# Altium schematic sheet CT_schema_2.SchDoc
size 566 x 421 mm
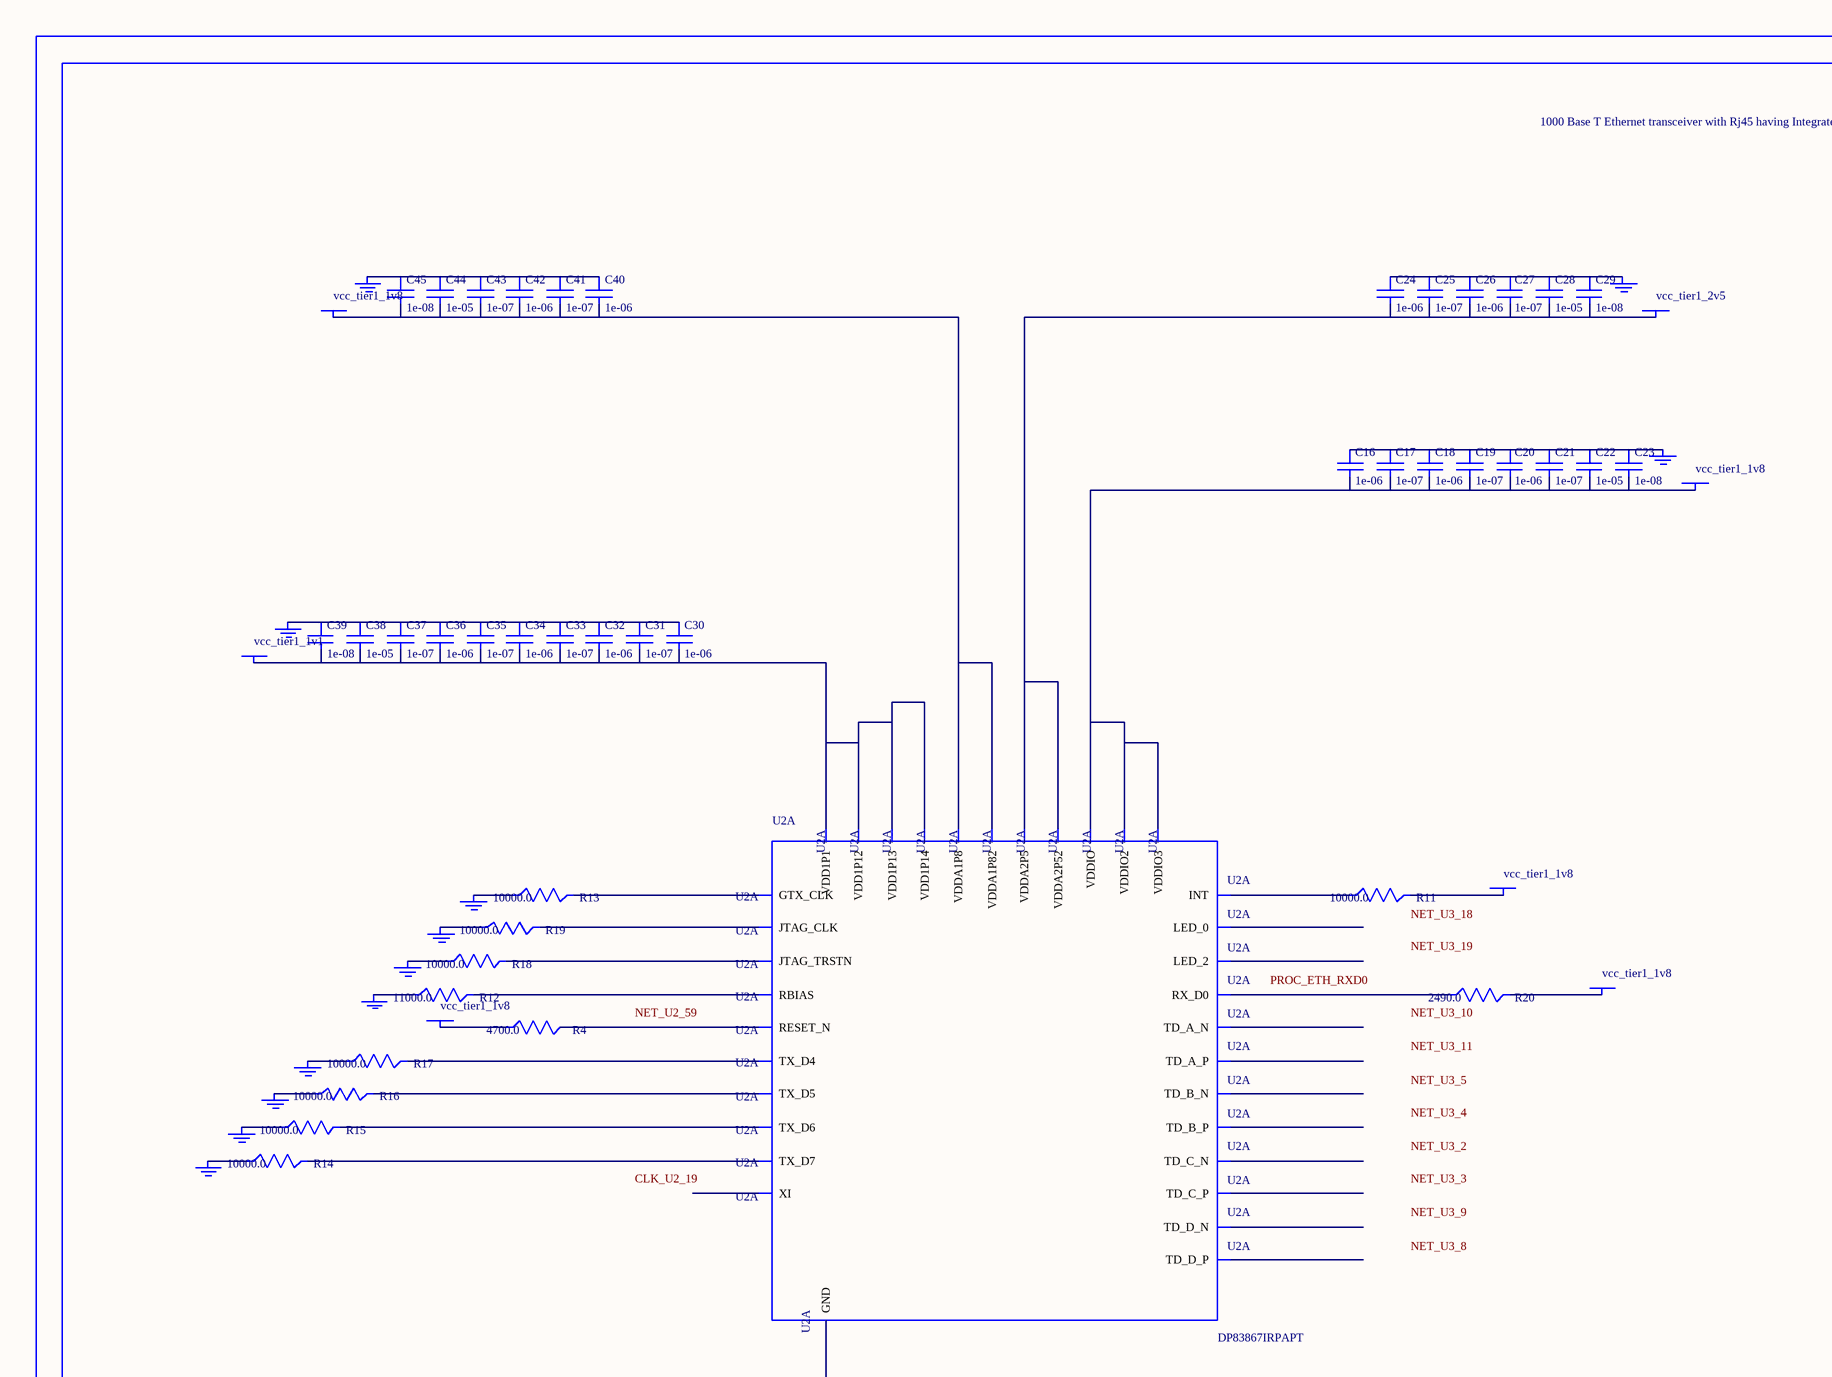
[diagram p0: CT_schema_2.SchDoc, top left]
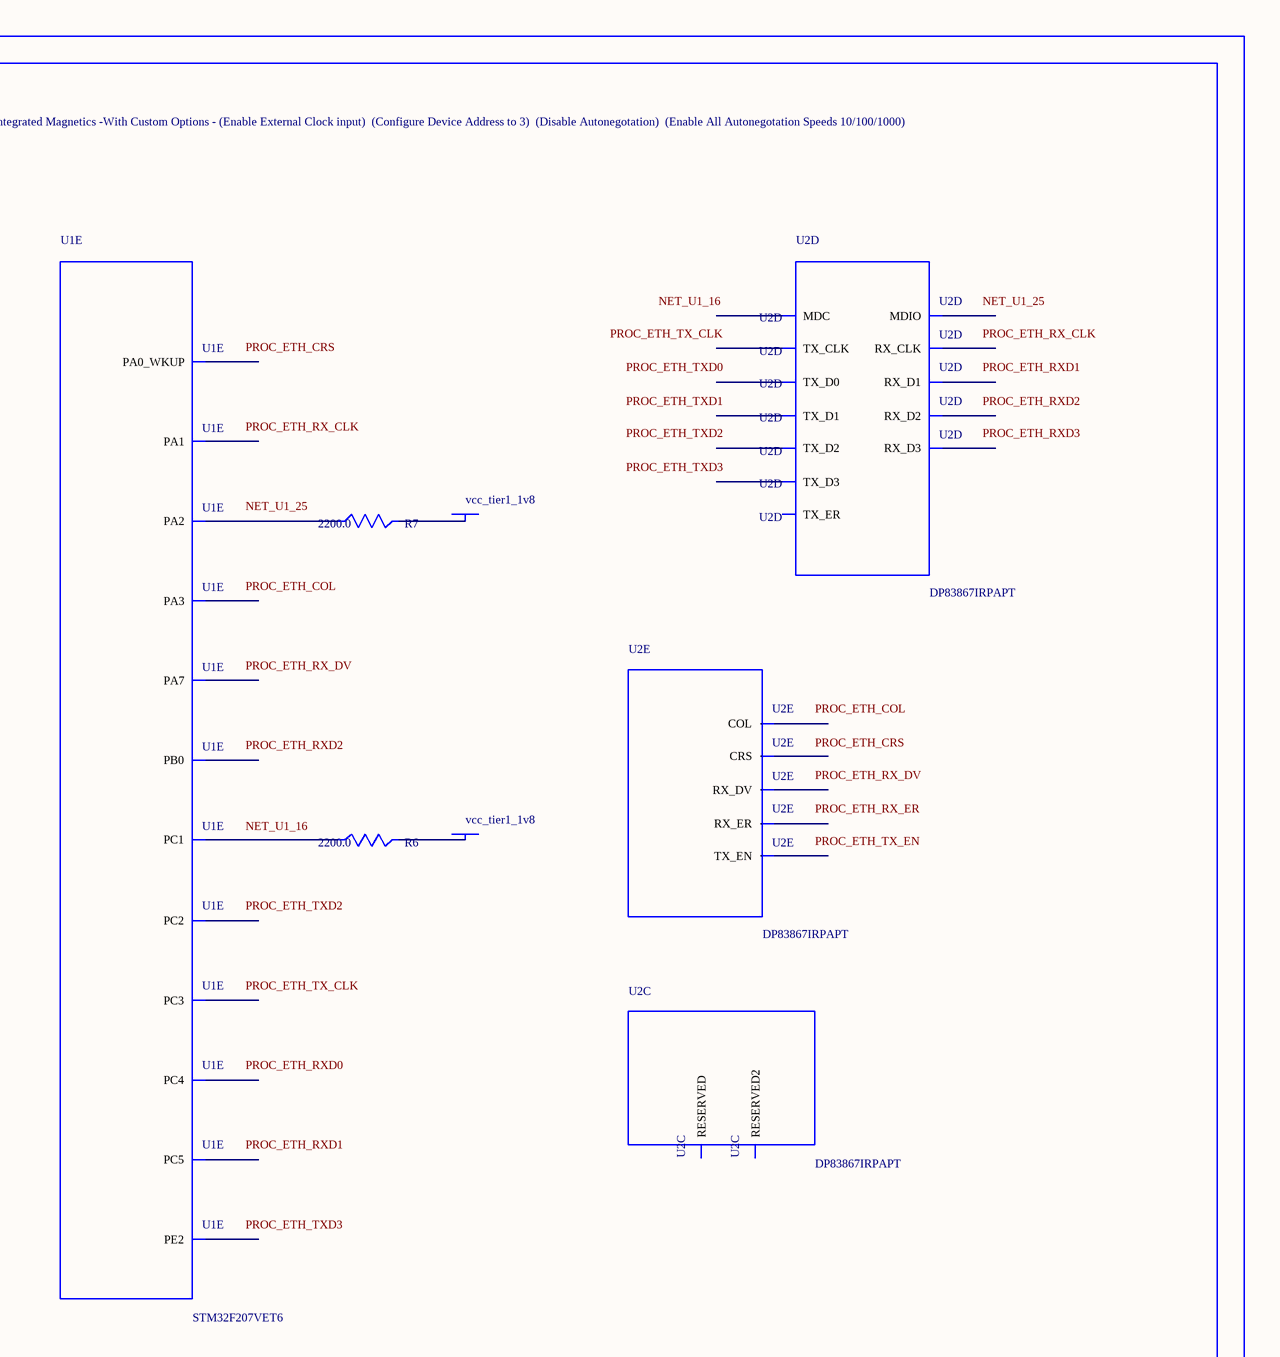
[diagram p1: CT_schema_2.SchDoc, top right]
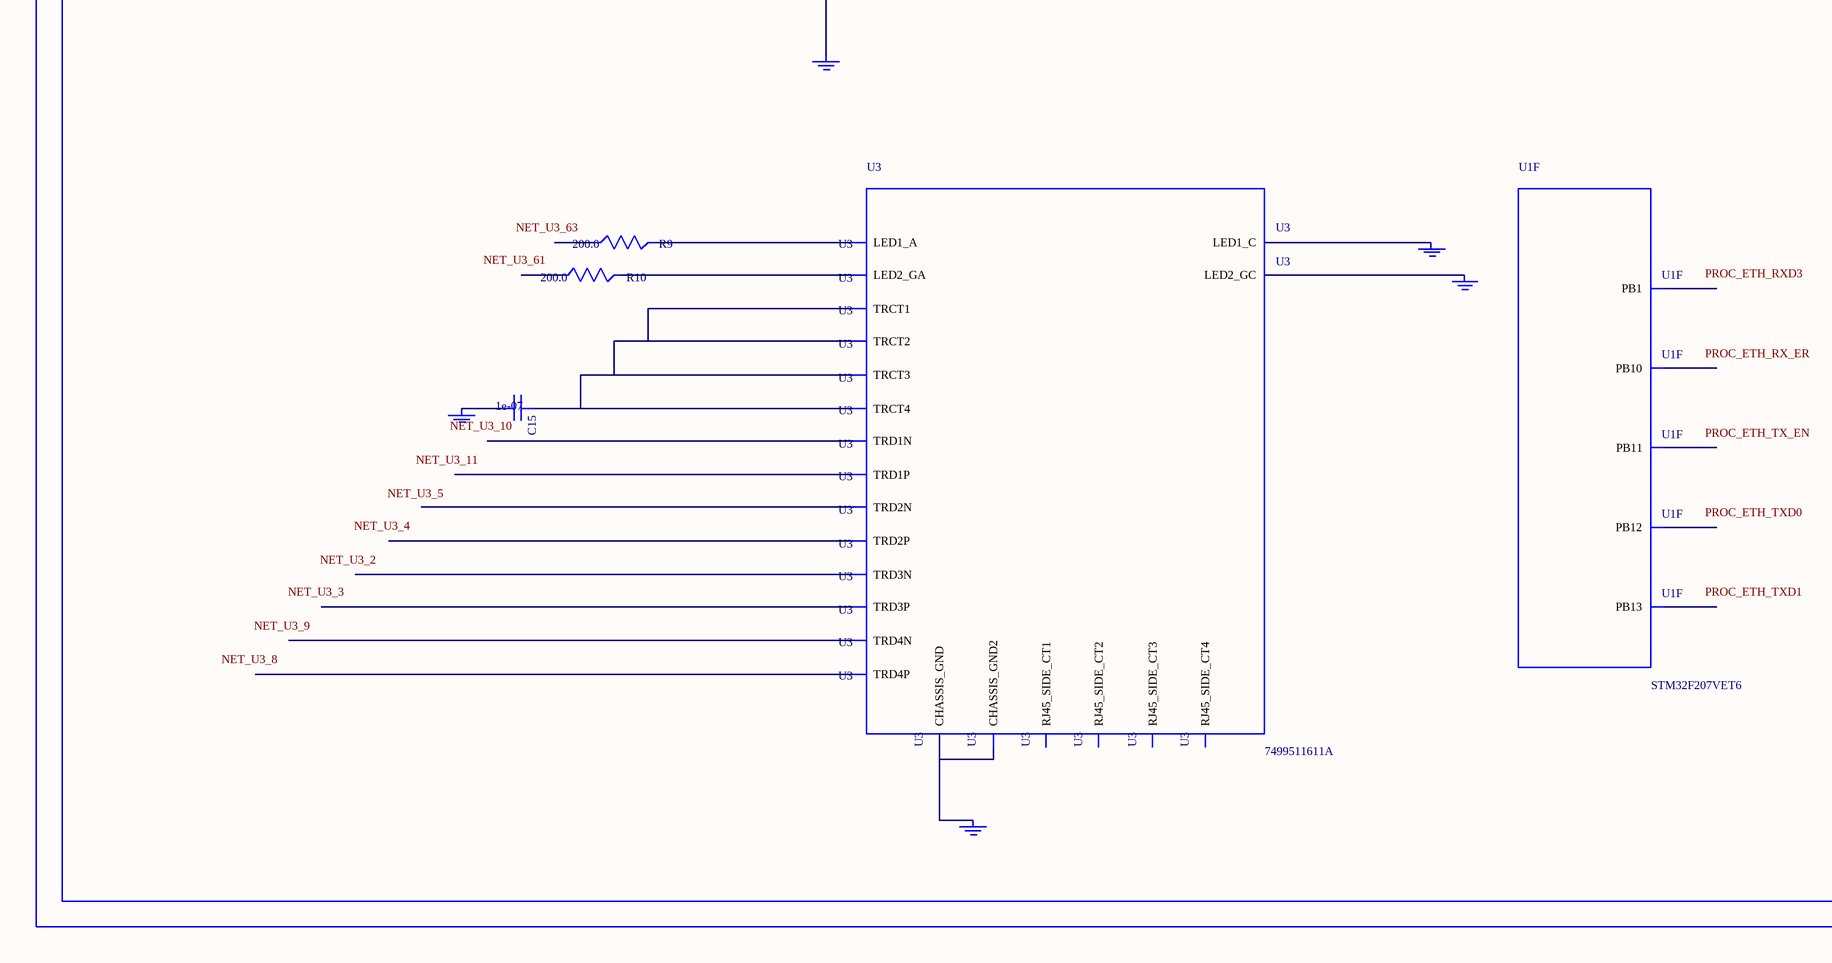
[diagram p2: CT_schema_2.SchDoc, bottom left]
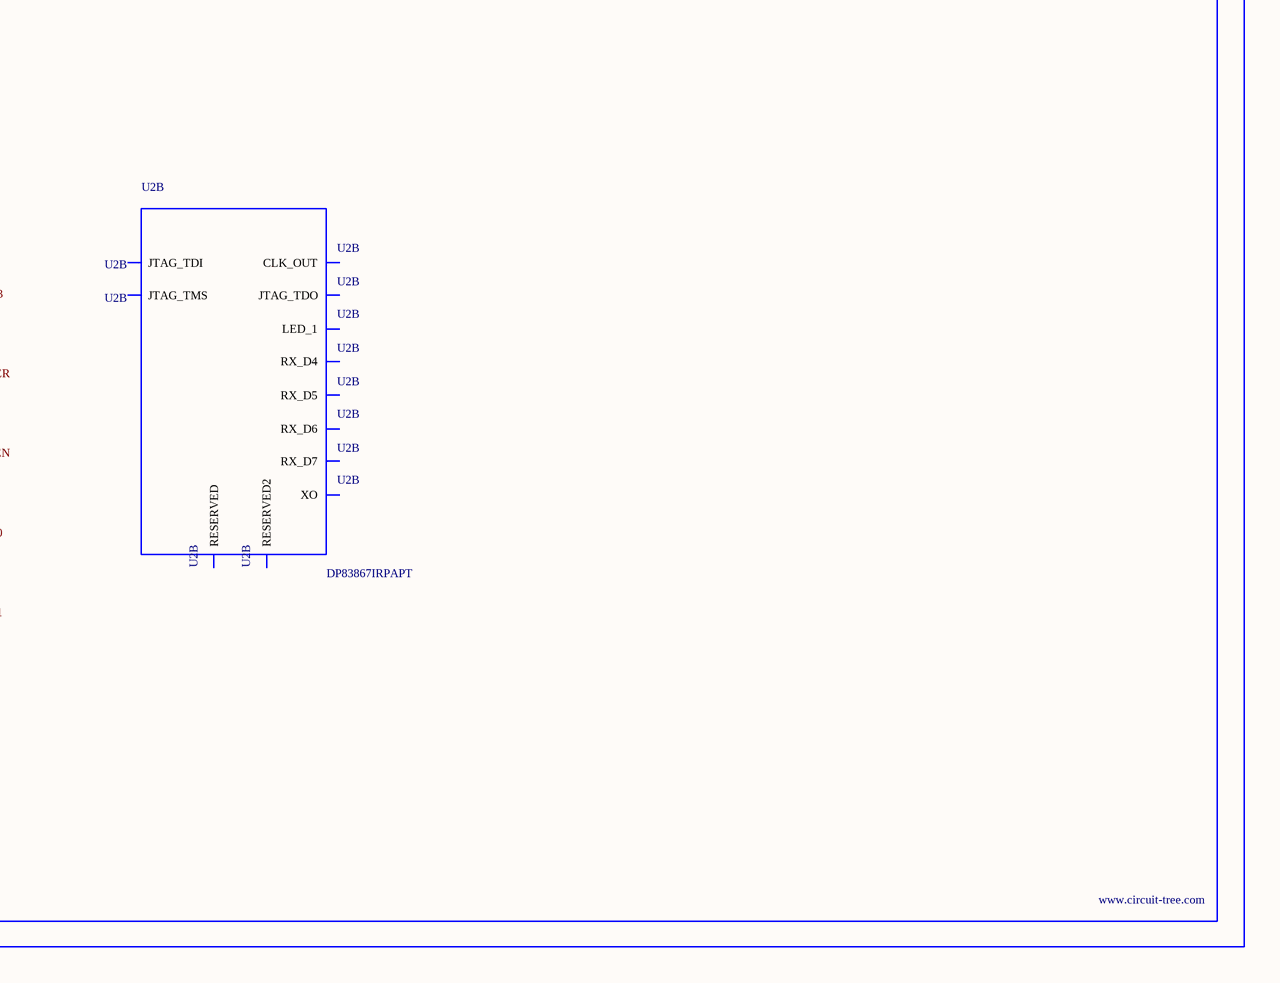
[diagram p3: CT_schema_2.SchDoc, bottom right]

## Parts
BORDER1  (no value)
C15  1e-07  [C0402]
C16  1e-06  [C0603]
C17  1e-07  [C0402]
C18  1e-06  [C0603]
C19  1e-07  [C0402]
C20  1e-06  [C0603]
C21  1e-07  [C0402]
C22  1e-05  [C0805]
C23  1e-08  [C0402]
C24  1e-06  [C0603]
C25  1e-07  [C0402]
C26  1e-06  [C0603]
C27  1e-07  [C0402]
C28  1e-05  [C0805]
C29  1e-08  [C0402]
C30  1e-06  [C0603]
C31  1e-07  [C0402]
C32  1e-06  [C0603]
C33  1e-07  [C0402]
C34  1e-06  [C0603]
C35  1e-07  [C0402]
C36  1e-06  [C0603]
C37  1e-07  [C0402]
C38  1e-05  [C0805]
C39  1e-08  [C0402]
C40  1e-06  [C0603]
C41  1e-07  [C0402]
C42  1e-06  [C0603]
C43  1e-07  [C0402]
C44  1e-05  [C0805]
C45  1e-08  [C0402]
GND_INSTANCE_1_0  (no value)
GND_INSTANCE_1_1  (no value)
GND_INSTANCE_1_2  (no value)
GND_INSTANCE_1_3  (no value)
GND_INSTANCE_1_4  (no value)
GND_INSTANCE_1_5  (no value)
GND_INSTANCE_1_6  (no value)
GND_INSTANCE_1_7  (no value)
GND_INSTANCE_1_8  (no value)
GND_INSTANCE_1_9  (no value)
GND_INSTANCE_1_10  (no value)
GND_INSTANCE_1_11  (no value)
GND_INSTANCE_1_12  (no value)
GND_INSTANCE_1_13  (no value)
GND_INSTANCE_1_14  (no value)
GND_INSTANCE_1_15  (no value)
GND_INSTANCE_1_16  (no value)
POWER_INSTANCE_1_0  vcc_tier1_2v5
POWER_INSTANCE_1_1  vcc_tier1_1v1
POWER_INSTANCE_1_2  vcc_tier1_1v8
POWER_INSTANCE_1_3  vcc_tier1_1v8
POWER_INSTANCE_1_4  vcc_tier1_1v8
POWER_INSTANCE_1_5  vcc_tier1_1v8
POWER_INSTANCE_1_6  vcc_tier1_1v8
POWER_INSTANCE_1_7  vcc_tier1_1v8
POWER_INSTANCE_1_8  vcc_tier1_1v8
R4  4700.0  [R0603]
R6  2200.0  [R0603]
R7  2200.0  [R0603]
R9  200.0  [R0603]
R10  200.0  [R0603]
R11  10000.0  [R0603]
R12  11000.0  [R0603]
R13  10000.0  [R0603]
R14  10000.0  [R0603]
R15  10000.0  [R0603]
R16  10000.0  [R0603]
R17  10000.0  [R0603]
R18  10000.0  [R0603]
R19  10000.0  [R0603]
R20  2490.0  [R0603]
U1  STM32F207VET6  [LQFP100]  (parts E,F of 9)
U2  DP83867IRPAPT  [HTQFP-64-EXP]  (parts A,B,C,D,E of 5)
U3  7499511611A  [7499511611A]

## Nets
NetC15_1: C15.1 U3.1(TRCT3) U3.6(TRCT2) U3.7(TRCT4) U3.12(TRCT1)
NetC15_2: C15.2 GND_INSTANCE_1_13.0(GND)
NetC16_1: C16.1 C17.1 C18.1 C19.1 C20.1 C21.1 C22.1 C23.1 GND_INSTANCE_1_4.0(GND)
NetC16_2: C16.2 C17.2 C18.2 C19.2 C20.2 C21.2 C22.2 C23.2 POWER_INSTANCE_1_3.0(PWR) U2.23(VDDIO) U2.41(VDDIO2) U2.57(VDDIO3)
NetC24_1: C24.1 C25.1 C26.1 C27.1 C28.1 C29.1 GND_INSTANCE_1_0.0(GND)
NetC24_2: C24.2 C25.2 C26.2 C27.2 C28.2 C29.2 POWER_INSTANCE_1_0.0(PWR) U2.4(VDDA2P5) U2.12(VDDA2P52)
NetC30_1: C30.1 C31.1 C32.1 C33.1 C34.1 C35.1 C36.1 C37.1 C38.1 C39.1 GND_INSTANCE_1_1.0(GND)
NetC30_2: C30.2 C31.2 C32.2 C33.2 C34.2 C35.2 C36.2 C37.2 C38.2 C39.2 POWER_INSTANCE_1_1.0(PWR) U2.8(VDD1P1) U2.29(VDD1P12) U2.42(VDD1P13) U2.58(VDD1P14)
NetC40_1: C40.1 C41.1 C42.1 C43.1 C44.1 C45.1 GND_INSTANCE_1_3.0(GND)
NetC40_2: C40.2 C41.2 C42.2 C43.2 C44.2 C45.2 POWER_INSTANCE_1_2.0(PWR) U2.17(VDDA1P8) U2.64(VDDA1P82)
NetGND_INSTANCE_1_2_0: GND_INSTANCE_1_2.0(GND) R12.1
NetGND_INSTANCE_1_5_0: GND_INSTANCE_1_5.0(GND) R18.1
NetGND_INSTANCE_1_6_0: GND_INSTANCE_1_6.0(GND) R19.1
NetGND_INSTANCE_1_7_0: GND_INSTANCE_1_7.0(GND) R14.1
NetGND_INSTANCE_1_8_0: GND_INSTANCE_1_8.0(GND) R15.1
NetGND_INSTANCE_1_9_0: GND_INSTANCE_1_9.0(GND) R16.1
NetGND_INSTANCE_1_10_0: GND_INSTANCE_1_10.0(GND) R17.1
NetGND_INSTANCE_1_11_0: GND_INSTANCE_1_11.0(GND) R13.1
NetGND_INSTANCE_1_12_0: GND_INSTANCE_1_12.0(GND) U2.EXP(GND)
NetGND_INSTANCE_1_14_0: GND_INSTANCE_1_14.0(GND) U3.17(LED1_C)
NetGND_INSTANCE_1_15_0: GND_INSTANCE_1_15.0(GND) U3.20(LED2_GC)
NetGND_INSTANCE_1_16_0: GND_INSTANCE_1_16.0(GND) U3.Z1(CHASSIS_GND) U3.Z2(CHASSIS_GND2)
NetPOWER_INSTANCE_1_4_0: POWER_INSTANCE_1_4.0(PWR) R20.2
NetPOWER_INSTANCE_1_5_0: POWER_INSTANCE_1_5.0(PWR) R11.2
NetPOWER_INSTANCE_1_6_0: POWER_INSTANCE_1_6.0(PWR) R4.1
NetPOWER_INSTANCE_1_7_0: POWER_INSTANCE_1_7.0(PWR) R6.2
NetPOWER_INSTANCE_1_8_0: POWER_INSTANCE_1_8.0(PWR) R7.2
NetR4_2: R4.2 U2.59(RESET_N)
NetR6_1: R6.1 U1.16(PC1)
NetR7_1: R7.1 U1.25(PA2)
NetR9_2: R9.2 U3.18(LED1_A)
NetR10_2: R10.2 U3.19(LED2_GA)
NetR11_1: R11.1 U2.60(INT)
NetR12_2: R12.2 U2.15(RBIAS)
NetR13_2: R13.2 U2.40(GTX_CLK)
NetR14_2: R14.2 U2.31(TX_D7)
NetR15_2: R15.2 U2.32(TX_D6)
NetR16_2: R16.2 U2.33(TX_D5)
NetR17_2: R17.2 U2.34(TX_D4)
NetR18_2: R18.2 U2.24(JTAG_TRSTN)
NetR19_2: R19.2 U2.25(JTAG_CLK)
NetR20_1: R20.1 U2.44(RX_D0)

Not connected (* = marked no-connect by the designer): R9 1; R10 1; U1 1(PE2) 17(PC2) 18(PC3) 23(PA0_WKUP) 24(PA1) 26(PA3) 32(PA7) 33(PC4) 34(PC5) 35(PB0) 36(PB1) 47(PB10) 48(PB11) 51(PB12) 52(PB13); U2 1(RESERVED) 2(TD_A_P) 3(TD_A_N) 5(TD_B_P) 6(TD_B_N) 7(RESERVED2) 9(RESERVED) 10(TD_C_P) 11(TD_C_N) 13(TD_D_P) 14(TD_D_N) 16(RESERVED2) 18(XO) 19(XI) 20(MDC) 21(MDIO) 22(CLK_OUT) 26(JTAG_TDO) 27(JTAG_TMS) 28(JTAG_TDI) 30(TX_CLK) 35(TX_D3) 36(TX_D2) 37(TX_D1) 38(TX_D0) 39(TX_ER) 43(RX_CLK) 45(RX_D1) 46(RX_D2) 47(RX_D3) 48(RX_D4) 49(RX_D5) 50(RX_D6) 51(RX_D7) 52(TX_EN) 53(RX_DV) 54(RX_ER) 55(COL) 56(CRS) 61(LED_2) 62(LED_1) 63(LED_0); U3 2(TRD3N) 3(TRD3P) 4(TRD2P) 5(TRD2N) 8(TRD4P) 9(TRD4N) 10(TRD1N) 11(TRD1P) 13(RJ45_SIDE_CT1) 14(RJ45_SIDE_CT2) 15(RJ45_SIDE_CT3) 16(RJ45_SIDE_CT4)

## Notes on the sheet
- Labels drawn without touching a wire or pin: CLK_U2_19, NET_U1_16, NET_U1_25, NET_U2_59, NET_U3_2, NET_U3_3, NET_U3_4, NET_U3_5, NET_U3_8, NET_U3_9, NET_U3_10, NET_U3_11, NET_U3_18, NET_U3_19, NET_U3_61, NET_U3_63, PROC_ETH_COL, PROC_ETH_CRS, PROC_ETH_RX_CLK, PROC_ETH_RX_DV, PROC_ETH_RX_ER, PROC_ETH_RXD0, PROC_ETH_RXD1, PROC_ETH_RXD2, PROC_ETH_RXD3, PROC_ETH_TX_CLK, PROC_ETH_TX_EN, PROC_ETH_TXD0, PROC_ETH_TXD1, PROC_ETH_TXD2, PROC_ETH_TXD3

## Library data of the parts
BORDER1 = BORDER_PAGE1
C15 C17 C19 C21 C25 C27 C31 C33 C35 C37 C41 C43 = C0402C104K3RACTU
C16 C18 C20 C24 C26 C30 C32 C34 C36 C40 C42 = C0603C105K3RACTU
C22 C28 C38 C44 = C0805C106K8RACTU
C23 C29 C39 C45 = C0402C103K3RAC
GND_INSTANCE_1_0-GND_INSTANCE_1_16 = GND
POWER_INSTANCE_1_0-POWER_INSTANCE_1_8 = PWR
R4 = RC0603JR-074K7L
R6 R7 = RC0603JR-072K2L
R9 R10 = RC0603JR-07200RL
R11 R13-R19 = RC0603JR-0710KL
R12 = RC0603JR-0711KL
R20 = ERA-3AED2490V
